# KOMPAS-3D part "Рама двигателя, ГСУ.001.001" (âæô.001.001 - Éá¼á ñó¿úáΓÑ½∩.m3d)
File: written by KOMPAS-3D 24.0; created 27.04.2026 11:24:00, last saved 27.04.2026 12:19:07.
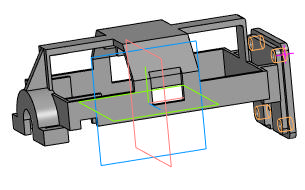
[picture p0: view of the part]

Document properties: Автор: User7; Полное имя файла: C:\Users\User7\Desktop\олимп\ГСУ.001.001 - Рама двигателя.m3d

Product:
- Part/product: Рама двигателя  | designation ГСУ.001.001
    Масса: 0.221971

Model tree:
1. Эскиз:1
2. Элемент выдавливания:1
     Расстояние 1 = 31
3. Элемент выдавливания:2
     Расстояние 1 = 15
4. Эскиз:3  (with: Ребро.Элемент выдавливания:1, Вершина.Элемент выдавливания:1)
5. Элемент выдавливания:3
     Расстояние 1 = 13
6. Элемент выдавливания:4  (with: Грань.Элемент выдавливания:3)
     Расстояние 1 = 11
7. Эскиз:4  (with: Грань.Элемент выдавливания:1, Ребро.Элемент выдавливания:3)
8. Элемент выдавливания:5
9. Эскиз:5  (with: Грань.Элемент выдавливания:3)
10. Элемент выдавливания:6
     Расстояние 1 = 10; Расстояние 2 = 1.5
11. Эскиз:6  (with: Ребро.Элемент выдавливания:6, Вершина.Элемент выдавливания:1, Вершина.Элемент выдавливания:6, Вершина.Элемент выдавливания:3)
12. Элемент выдавливания:7
     Расстояние 1 = 5
13. Элемент выдавливания:8
     Расстояние 1 = 2; Расстояние 2 = 1
14. Эскиз:7  (with: Грань.Элемент выдавливания:1, Вершина.Элемент выдавливания:7)
15. Элемент выдавливания:9
     Расстояние 1 = 1
16. Эскиз:8  (with: Грань.Элемент выдавливания:6, Ребро.Элемент выдавливания:6)
17. Элемент выдавливания:10  (with: Грань.Элемент выдавливания:6)
     Расстояние 2 = 7
18. Эскиз:9  (with: Грань.Элемент выдавливания:3, Ребро.Элемент выдавливания:3)
19. Элемент выдавливания:11
     Расстояние 1 = 8
20. Эскиз:10  (with: Грань.Элемент выдавливания:11)
21. Элемент выдавливания:12
     Расстояние 1 = 2.5
22. Эскиз:11  (with: Грань.Элемент выдавливания:12)
23. Элемент выдавливания:13
     Расстояние 1 = 3
24. Элемент выдавливания:14
     Расстояние 2 = 108.5
25. Зеркальный массив:1
26. Экземпляр ( 1 )
27. Экземпляр ( 2 )  (with: Элемент выдавливания:3, Элемент выдавливания:4, Элемент выдавливания:1, Элемент выдавливания:2, Элемент выдавливания:5, Элемент выдавливания:6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)
28. Эскиз:12  (with: Грань.Элемент выдавливания:13)
29. Скругление:1  (with: Ребро.Элемент выдавливания:7, Ребро.Элемент выдавливания:13)
     Радиус = 1
30. Скругление:2  (with: Ребро.Элемент выдавливания:13, Ребро.Элемент выдавливания:12)  (labels: Ребро.Элемент выдавливания:12.Экземпляр ( 2 ); Ребро.Элемент выдавливания:13.Экземпляр ( 2 ))
     Радиус = 3
31. Отверстие:1  (with: Грань.Элемент выдавливания:13, Ребро.Элемент выдавливания:13, Грань.Элемент выдавливания:12)  (labels: M6)
     Глубина выреза = 5.5; Диаметр отверстия = 4.91747; Угол конуса дна = 118; Расстояние 1 = 6; Расстояние 2 = 38
32. M6  (with: Грань.Отверстие:1, Грань.Элемент выдавливания:13, Грань.Элемент выдавливания:12)  (labels: cil0_24705-2004 coarse)
     Длина резьбы = 5.5; Шаг резьбы = 1; Номинальный диаметр резьбы = 6
33. Массив по концентрической сетке:1  (with: Отверстие:1, Эскиз:12)  (labels: M6)  (2 pattern instances)
34. Отверстие:1  (with: Эскиз:12)  (labels: M6)
35. Отверстие:1  (with: Эскиз:12)  (labels: M6)

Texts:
  ГСУ.001.001
  Шаг 1
  Режим 1
  Шаг 2
  Режим 2
  Шаг по оси
  Номер 1
  Номер 2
